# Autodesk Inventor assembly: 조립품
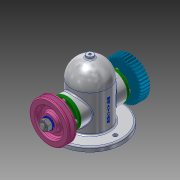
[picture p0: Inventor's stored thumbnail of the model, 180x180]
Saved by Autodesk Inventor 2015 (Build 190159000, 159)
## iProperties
Created: 2019-11
Part Number: 조립품
Document SubType Name: Assembly
Designer: LINEART-SSD.D4.16.07
Author: LINEART-SSD.D4.16.07
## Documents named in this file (14)
- C:\Users\LINEART-SSD.D4.16.07\Desktop\491104V1014\조립품.iam
- C:\Users\LINEART-SSD.D4.16.07\Desktop\491104V1014\본체.ipt
- C:\Users\LINEART-SSD.D4.16.07\Desktop\491104V1014\축.ipt
- C:\Users\LINEART-SSD.D4.16.07\Desktop\491104V1014\베어링 6203.ipt
- C:\Users\LINEART-SSD.D4.16.07\Desktop\491104V1014\부시.ipt
- C:\Users\LINEART-SSD.D4.16.07\Desktop\491104V1014\커버.ipt
- C:\Users\LINEART-SSD.D4.16.07\Desktop\491104V1014\오일 실 26 38 8.ipt
- C:\Users\LINEART-SSD.D4.16.07\Desktop\491104V1014\볼트 M4.ipt
- C:\Users\LINEART-SSD.D4.16.07\Desktop\491104V1014\키 5x5x12.ipt
- C:\Users\LINEART-SSD.D4.16.07\Desktop\491104V1014\V-벨트풀리.ipt
- V-벨트풀리.ipt
- C:\Users\LINEART-SSD.D4.16.07\Desktop\491104V1014\스퍼기어.ipt
- C:\Users\LINEART-SSD.D4.16.07\Desktop\491104V1014\와셔 12x24.ipt
- C:\Users\LINEART-SSD.D4.16.07\Desktop\491104V1014\너트 M12x1.25.ipt
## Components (1 placed, 1 different names)
1. V-벨트풀리:1
